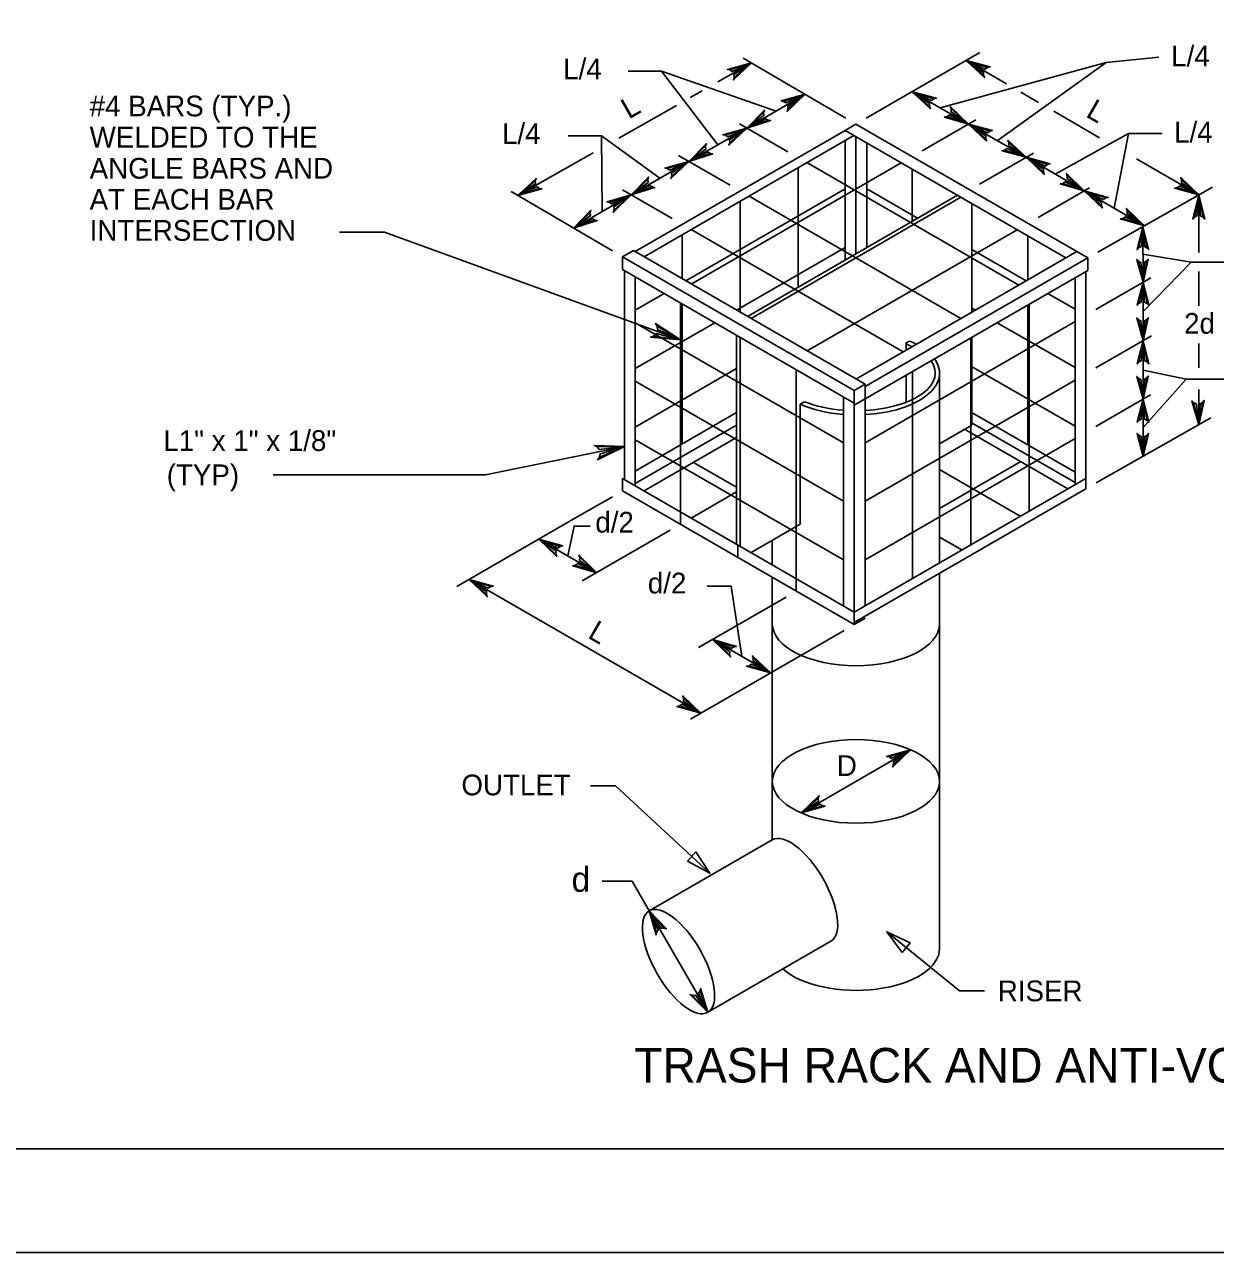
# Model space of a CAD drawing. Extents: x 636462 to 639890, y 299944 to 300538.
# Drawn here: x 637624.9 to 637797.1, y 299944.4 to 300122 of the extents above; entities that cross this region are included whole.
import ezdxf

# ---------------------------------------------------------------- set-up
doc = ezdxf.new("R2010")
doc.units = 0
for name, color, linetype in [('1', 7, 'Continuous'), ('Default', 7, 'Continuous'), ('PLT-BNDY', 7, 'Continuous')]:
    doc.layers.add(name, color=color, linetype=linetype)

msp = doc.modelspace()

# ---------------------------------------------------------------- linework, layer by layer
at = {"layer": '1'}
msp.add_lwpolyline([(638128.91, 299959.45), (638128.91, 300523.45), (637342.91, 300523.45), (637342.91, 299959.45), (638128.91, 299959.45), (638128.91, 299985.81), (637928.91, 299985.81), (637928.91, 300050.49), (638128.91, 300050.49), (638128.91, 300079.45), (637928.91, 300079.45), (637928.91, 299959.45), (638007.72, 299959.45), (638007.72, 299985.81), (638007.72, 299959.45), (638084.72, 299959.45), (638084.72, 299985.81), (638084.72, 299973.49), (638128.91, 299973.49)], dxfattribs=at)
at = {"layer": 'Default'}
for p, q in [((637746.61, 300108.45), (637763.05, 300117.94)), ((637743.68, 300108.46), (637728.84, 300117.16)), ((637765.56, 300105.2), (637781.31, 300116.52)), ((637733.58, 300109.48), (637717.03, 300115.25)), ((637729.36, 300107.04), (637737.79, 300111.91)), ((637720.99, 300102.21), (637729.36, 300107.04)), ((637735.3, 300103.61), (637728.3, 300107.66)), ((637743.57, 300106.69), (637745.14, 300107.6)), ((637745.14, 300107.6), (637778.64, 300088.26)), ((637754.72, 300103.76), (637762.45, 300108.22)), ((637761.39, 300107.61), (637769.73, 300102.8)), ((637708.46, 300094.97), (637708.33, 300105.89)), ((637713.22, 300089.17), (637743.57, 300106.69)), ((637714.5, 300088.43), (637744.85, 300105.95)), ((637743.57, 300106.69), (637775.5, 300088.26)), ((637743.57, 300105.22), (637743.57, 300087.96)), ((637745.14, 300105.79), (637745.14, 300088.87)), ((637782.49, 300095.43), (637784.55, 300106.23)), ((637746.71, 300104.88), (637746.71, 300089.77)), ((637763, 300098.91), (637770.79, 300103.41)), ((637712.62, 300097.37), (637720.99, 300102.21)), ((637726.93, 300098.78), (637719.49, 300103.07)), ((637721.33, 300084.48), (637751.69, 300102.01)), ((637768.7, 300084.33), (637738.05, 300102.03)), ((637769.72, 300102.8), (637778.13, 300097.94)), ((637736.77, 300101.29), (637736.77, 300084.03)), ((637753.26, 300101.1), (637753.26, 300093.55)), ((637718.56, 300093.94), (637711.36, 300098.1)), ((637720.55, 300084.94), (637743.57, 300098.23)), ((637754.04, 300094), (637746.71, 300098.23)), ((637771.47, 300094.09), (637778.89, 300098.38)), ((637780.11, 300089.1), (637796.7, 300098.5)), ((637709.93, 300089.27), (637695.28, 300097.85)), ((637704.3, 300092.57), (637712.62, 300097.37)), ((637728.4, 300096.45), (637728.4, 300080.4)), ((637729.44, 300079.8), (637759.8, 300097.33)), ((637760.32, 300079.5), (637729.68, 300097.19)), ((637729.97, 300079.5), (637760.32, 300097.02)), ((637778.13, 300097.94), (637786.85, 300092.91)), ((637761.89, 300096.12), (637761.89, 300080.4)), ((637786.63, 300092.79), (637786.64, 300084.73)), ((637720.02, 300091.62), (637720.02, 300085.24)), ((637751.95, 300074.66), (637721.3, 300092.36)), ((637738.08, 300074.81), (637768.43, 300092.34)), ((637770, 300091.43), (637770, 300085.09)), ((637711.39, 300088.41), (637712.96, 300089.32)), ((637712.96, 300089.32), (637746.45, 300069.98)), ((637713.22, 300089.17), (637713.22, 300089.17)), ((637727.87, 300080.71), (637743.57, 300089.77)), ((637752.39, 300074.92), (637777.07, 300089.17)), ((637769.74, 300084.94), (637761.89, 300089.47)), ((637711.39, 300086.6), (637711.39, 300088.41)), ((637744.88, 300069.07), (637711.39, 300088.41)), ((637714.5, 300088.43), (637714.5, 300088.43)), ((637746.45, 300069.68), (637778.64, 300088.26)), ((637778.64, 300086.45), (637778.64, 300088.26)), ((637786.64, 300080.51), (637793.6, 300087.62)), ((637744.88, 300067.26), (637711.39, 300086.6)), ((637711.65, 300086.45), (637711.65, 300056.23)), ((637711.65, 300086.45), (637711.65, 300086.45)), ((637744.88, 300066.96), (637778.64, 300086.45)), ((637778.38, 300086.3), (637778.38, 300056.38)), ((637713.22, 300085.54), (637713.22, 300055.32)), ((637776.81, 300085.39), (637776.81, 300055.48)), ((637779.84, 300080.8), (637787.76, 300085.38)), ((637786.64, 300084.73), (637786.64, 300076.27)), ((637713.22, 300080.71), (637717.41, 300083.12)), ((637776.81, 300080.86), (637772.88, 300083.12)), ((637719.76, 300081.76), (637719.76, 300051.55)), ((637720.02, 300081.61), (637720.02, 300061.37)), ((637761.89, 300081.01), (637762.41, 300080.71)), ((637770, 300081.46), (637770, 300061.22)), ((637770.2, 300081.58), (637770.2, 300051.66)), ((637713.22, 300072.25), (637724.73, 300078.89)), ((637743.31, 300061.52), (637713.22, 300078.89)), ((637746.45, 300061.52), (637776.81, 300079.05)), ((637776.81, 300072.4), (637765.56, 300078.89)), ((637727.87, 300077.08), (637727.87, 300046.86)), ((637728.4, 300076.78), (637728.4, 300046.56)), ((637761.76, 300076.7), (637761.76, 300046.79)), ((637761.89, 300076.83), (637761.89, 300064.09)), ((637779.84, 300072.34), (637787.86, 300076.98)), ((637745.14, 300070.74), (637752.39, 300074.92)), ((637752.39, 300075.96), (637752.88, 300076.24)), ((637752.39, 300074.92), (637752.39, 300075.96)), ((637752.5, 300075.78), (637752.39, 300075.96)), ((637753.28, 300075.44), (637753.28, 300075.44)), ((637753.88, 300075.78), (637753.88, 300075.78)), ((637786.64, 300076.27), (637786.65, 300067.81)), ((637755.99, 300073.37), (637755.99, 300073.37)), ((637756.49, 300073.66), (637756.49, 300073.66)), ((637713.22, 300063.79), (637727.87, 300072.25)), ((637736.51, 300072.1), (637736.51, 300041.88)), ((637753.32, 300071.83), (637753.32, 300041.92)), ((637757.22, 300044.16), (637757.22, 300071.61)), ((637776.81, 300063.93), (637761.76, 300072.62)), ((637743.31, 300053.06), (637713.22, 300070.43)), ((637746.45, 300069.98), (637744.88, 300069.07)), ((637746.45, 300053.06), (637776.81, 300070.58)), ((637746.45, 300069.98), (637746.45, 300037.95)), ((637746.45, 300069.68), (637746.45, 300069.68)), ((637752.39, 300067.39), (637752.39, 300071.29)), ((637786.65, 300063.71), (637792.89, 300070.72)), ((637743.31, 300068.17), (637743.31, 300044.6)), ((637744.88, 300069.07), (637744.88, 300067.26)), ((637779.84, 300063.87), (637787.74, 300068.45)), ((637786.65, 300067.81), (637786.66, 300059.56)), ((637737.06, 300067.11), (637737.68, 300067.46)), ((637737.06, 300049.75), (637737.06, 300067.11)), ((637737.68, 300067.46), (637737.68, 300067.46)), ((637743.31, 300066.24), (637743.31, 300066.24)), ((637744.88, 300067.26), (637744.88, 300037.04)), ((637746.45, 300066.2), (637746.45, 300066.2)), ((637713.22, 300057.44), (637727.87, 300065.9)), ((637743.31, 300065.63), (637743.31, 300065.63)), ((637746.45, 300065.6), (637746.45, 300065.6)), ((637776.81, 300057.29), (637762.02, 300065.82)), ((637776.81, 300055.78), (637762.02, 300064.31)), ((637779.85, 300055.71), (637796.43, 300065.11)), ((637713.22, 300055.63), (637727.87, 300064.09)), ((637757.22, 300061.39), (637761.89, 300064.09)), ((637775.76, 300054.87), (637760.85, 300063.48)), ((637778.38, 300063.03), (637778.37, 300063.03)), ((637743.31, 300044.6), (637713.22, 300061.97)), ((637714.53, 300054.57), (637727.87, 300062.27)), ((637746.45, 300044.6), (637776.81, 300062.12)), ((637727.87, 300055.1), (637721.66, 300058.69)), ((637757.22, 300052.02), (637768.96, 300058.8)), ((637768.89, 300050.9), (637757.22, 300057.65)), ((637711.39, 300056.38), (637711.39, 300054.57)), ((637744.88, 300037.04), (637711.39, 300056.38)), ((637744.88, 300037.04), (637778.38, 300056.38)), ((637778.38, 300056.38), (637778.38, 300054.87)), ((637709.92, 300053.72), (637704.6, 300050.65)), ((637711.39, 300054.57), (637744.88, 300035.23)), ((637721.33, 300050.64), (637727.87, 300054.42)), ((637778.38, 300054.87), (637744.88, 300035.53)), ((637704.6, 300050.65), (637687.43, 300040.74)), ((637719.76, 300051.55), (637719.76, 300049.73)), ((637718.29, 300048.89), (637705.57, 300041.54)), ((637729.97, 300045.65), (637737.06, 300049.75)), ((637737.06, 300049.75), (637737.06, 300049.75)), ((637707.65, 300042.74), (637699.28, 300047.58)), ((637728.04, 300046.76), (637728.04, 300044.95)), ((637733.04, 300047.43), (637733.04, 300043.88)), ((637760.45, 300046.03), (637757.22, 300047.9)), ((637743.31, 300044.76), (637743.31, 300037.95)), ((637733.04, 300042.07), (637733.04, 300035.34)), ((637736.51, 300041.88), (637736.51, 300040.06)), ((637757.22, 300035.34), (637757.22, 300042.65)), ((637735.04, 300039.22), (637722.39, 300031.92)), ((637744.88, 300035.23), (637744.88, 300037.04)), ((637744.88, 300035.23), (637746.45, 300036.14)), ((637733.04, 300035.34), (637733.04, 300013)), ((637743.42, 300034.38), (637738.1, 300031.31)), ((637757.22, 300035.34), (637757.22, 300012.56)), ((637724.4, 300033.07), (637732.77, 300028.24)), ((637738.09, 300031.31), (637721.19, 300021.55)), ((637706.76, 300011.93), (637710.36, 300011.93)), ((637724.03, 299999.27), (637710.36, 300011.93)), ((637733.04, 300012.56), (637733.04, 300004.1)), ((637757.22, 300012.56), (637757.22, 299988.39)), ((637733.04, 300004.1), (637715.25, 299993.83)), ((637733.04, 300004.1), (637733.04, 300004.1)), ((637708.46, 299998.14), (637712.76, 299998.14)), ((637749.59, 299990.81), (637760.1, 299982.27)), ((637741.5, 299989.45), (637723.71, 299979.17)), ((637734.57, 299985.45), (637734.57, 299985.45)), ((637763.7, 299982.27), (637760.1, 299982.27))]:
    msp.add_line(p, q, dxfattribs=at)
for points in [[(637730.02, 300116.47), (637725.16, 300113.71)], [(637726.89, 300115.45), (637726.55, 300115.51), (637730.02, 300116.47), (637726.89, 300115.45), (637727.24, 300115.22), (637730.02, 300116.47), (637727.5, 300114.76), (637727.53, 300114.35), (637730.02, 300116.47), (637727.41, 300113.99), (637727.53, 300114.35)], [(637788.91, 300117.26), (637781.31, 300116.52), (637757.33, 300109.95)], [(637763.57, 300114.66), (637763.7, 300114.34), (637761.05, 300116.79), (637763.57, 300114.66), (637763.58, 300115.08), (637761.05, 300116.79), (637763.83, 300115.54), (637764.17, 300115.78), (637761.05, 300116.79), (637764.54, 300115.87), (637764.17, 300115.78)], [(637766.89, 300113.41), (637761.05, 300116.79)], [(637712.2, 300115.25), (637717.03, 300115.25), (637725.18, 300104.62)], [(637722.9, 300112.42), (637721.18, 300111.44)], [(637755.78, 300110.15), (637755.9, 300109.83), (637753.27, 300112.29), (637755.78, 300110.15), (637755.79, 300110.57), (637753.27, 300112.29), (637756.04, 300111.03), (637756.38, 300111.27), (637753.27, 300112.29), (637756.76, 300111.35), (637756.38, 300111.27)], [(637761.39, 300107.61), (637753.27, 300112.29)], [(637771.54, 300110.73), (637768.99, 300112.2)], [(637734.66, 300110.89), (637734.32, 300110.95), (637737.79, 300111.91), (637734.66, 300110.89), (637735.02, 300110.66), (637737.79, 300111.91), (637735.28, 300110.2), (637735.3, 300109.79), (637737.79, 300111.91), (637735.18, 300109.43), (637735.3, 300109.79)], [(637719.19, 300110.31), (637710.87, 300105.58)], [(637732.46, 300108.18), (637732.8, 300108.13), (637729.36, 300107.04), (637732.46, 300108.18), (637732.09, 300108.39), (637729.36, 300107.04), (637731.82, 300108.84), (637731.78, 300109.25), (637729.36, 300107.04), (637731.89, 300109.62), (637731.78, 300109.25)], [(637758.92, 300109.79), (637758.8, 300110.12), (637761.39, 300107.61), (637758.92, 300109.79), (637758.9, 300109.37), (637761.39, 300107.61), (637758.64, 300108.92), (637758.29, 300108.68), (637761.39, 300107.61), (637757.92, 300108.61), (637758.29, 300108.68)], [(637780.37, 300105.63), (637773.73, 300109.47)], [(637726.24, 300106.01), (637725.89, 300106.07), (637729.36, 300107.04), (637726.24, 300106.01), (637726.59, 300105.78), (637729.36, 300107.04), (637726.85, 300105.33), (637726.88, 300104.91), (637729.36, 300107.04), (637726.76, 300104.55), (637726.88, 300104.91)], [(637763.89, 300105.47), (637764.02, 300105.14), (637761.39, 300107.61), (637763.89, 300105.47), (637763.9, 300105.89), (637761.39, 300107.61), (637764.15, 300106.35), (637764.5, 300106.59), (637761.39, 300107.61), (637764.87, 300106.67), (637764.5, 300106.59)], [(637703.5, 300105.89), (637708.33, 300105.89), (637716.8, 300099.79)], [(637767.23, 300104.95), (637767.11, 300105.28), (637769.73, 300102.8), (637767.23, 300104.95), (637767.22, 300104.53), (637769.73, 300102.8), (637766.96, 300104.07), (637766.62, 300103.83), (637769.73, 300102.8), (637766.25, 300103.75), (637766.62, 300103.83)], [(637789.39, 300106.23), (637784.55, 300106.23), (637773.93, 300100.37)], [(637696.26, 300097.28), (637707.14, 300103.46)], [(637724.08, 300103.34), (637724.43, 300103.29), (637720.99, 300102.21), (637724.08, 300103.34), (637723.72, 300103.56), (637720.99, 300102.21), (637723.44, 300104), (637723.4, 300104.42), (637720.99, 300102.21), (637723.51, 300104.78), (637723.4, 300104.42)], [(637717.86, 300101.19), (637717.51, 300101.25), (637720.99, 300102.21), (637717.86, 300101.19), (637718.21, 300100.96), (637720.99, 300102.21), (637718.47, 300100.51), (637718.49, 300100.09), (637720.99, 300102.21), (637718.37, 300099.73), (637718.49, 300100.09)], [(637772.23, 300100.66), (637772.35, 300100.33), (637769.73, 300102.8), (637772.23, 300100.66), (637772.24, 300101.08), (637769.73, 300102.8), (637772.49, 300101.54), (637772.83, 300101.77), (637769.73, 300102.8), (637773.21, 300101.86), (637772.83, 300101.77)], [(637794.69, 300097.36), (637785.7, 300102.56)], [(637715.71, 300098.51), (637716.05, 300098.46), (637712.62, 300097.37), (637715.71, 300098.51), (637715.35, 300098.72), (637712.62, 300097.37), (637715.07, 300099.17), (637715.03, 300099.58), (637712.62, 300097.37), (637715.14, 300099.95), (637715.03, 300099.58)], [(637712.62, 300097.37), (637716.82, 300099.79)], [(637775.68, 300100.14), (637775.56, 300100.47), (637778.13, 300097.94), (637775.68, 300100.14), (637775.66, 300099.72), (637778.13, 300097.94), (637775.4, 300099.26), (637775.05, 300099.03), (637778.13, 300097.94), (637774.68, 300098.96), (637775.05, 300099.03)], [(637792.22, 300099.54), (637792.1, 300099.87), (637794.69, 300097.36), (637792.22, 300099.54), (637792.21, 300099.12), (637794.69, 300097.36), (637791.95, 300098.66), (637791.6, 300098.43), (637794.69, 300097.36), (637791.23, 300098.36), (637791.6, 300098.43)], [(637699.39, 300098.3), (637699.74, 300098.24), (637696.26, 300097.28), (637699.39, 300098.3), (637699.04, 300098.53), (637696.26, 300097.28), (637698.78, 300098.98), (637698.76, 300099.4), (637696.26, 300097.28), (637698.88, 300099.76), (637698.76, 300099.4)], [(637709.5, 300096.29), (637709.16, 300096.35), (637712.62, 300097.37), (637709.5, 300096.29), (637709.86, 300096.07), (637712.62, 300097.37), (637710.13, 300095.62), (637710.16, 300095.21), (637712.62, 300097.37), (637710.05, 300094.84), (637710.16, 300095.21)], [(637780.64, 300095.8), (637780.76, 300095.47), (637778.13, 300097.94), (637780.64, 300095.8), (637780.65, 300096.22), (637778.13, 300097.94), (637780.9, 300096.68), (637781.24, 300096.92), (637778.13, 300097.94), (637781.62, 300097), (637781.24, 300096.92)], [(637794.06, 300094.13), (637793.83, 300093.86), (637794.7, 300097.36), (637794.06, 300094.13), (637794.43, 300094.33), (637794.7, 300097.36), (637794.95, 300094.33), (637795.33, 300094.15), (637794.7, 300097.36), (637795.58, 300093.87), (637795.33, 300094.15)], [(637794.7, 300097.36), (637794.7, 300089.04)], [(637707.39, 300093.7), (637707.74, 300093.65), (637704.3, 300092.57), (637707.39, 300093.7), (637707.03, 300093.92), (637704.3, 300092.57), (637706.75, 300094.37), (637706.71, 300094.78), (637704.3, 300092.57), (637706.82, 300095.14), (637706.71, 300094.78)], [(637784.37, 300095.08), (637784.25, 300095.41), (637786.85, 300092.91), (637784.37, 300095.08), (637784.35, 300094.66), (637786.85, 300092.91), (637784.09, 300094.21), (637783.75, 300093.97), (637786.85, 300092.91), (637783.38, 300093.9), (637783.75, 300093.97)], [(637786, 300089.72), (637785.79, 300089.47), (637786.63, 300092.79), (637786, 300089.72), (637786.36, 300089.91), (637786.63, 300092.79), (637786.86, 300089.91), (637787.21, 300089.73), (637786.63, 300092.79), (637787.45, 300089.46), (637787.21, 300089.73)], [(637719.76, 300076.39), (637676.96, 300091.99), (637670.45, 300091.99)], [(637787.18, 300087.81), (637787.39, 300088.07), (637786.64, 300084.73), (637787.18, 300087.81), (637786.83, 300087.62), (637786.64, 300084.73), (637786.34, 300087.6), (637785.98, 300087.77), (637786.64, 300084.73), (637785.73, 300088.03), (637785.98, 300087.77)], [(637798.44, 300087.62), (637793.6, 300087.62), (637786.63, 300088.82)], [(637794.7, 300086.31), (637794.7, 300081.31)], [(637786.01, 300081.66), (637785.79, 300081.41), (637786.64, 300084.73), (637786.01, 300081.66), (637786.36, 300081.85), (637786.64, 300084.73), (637786.86, 300081.85), (637787.22, 300081.67), (637786.64, 300084.73), (637787.46, 300081.4), (637787.22, 300081.67)], [(637716.37, 300078.41), (637716.15, 300078.77), (637719.76, 300076.39), (637716.37, 300078.41), (637716.44, 300077.91), (637719.76, 300076.39), (637716.23, 300077.32), (637715.87, 300076.96), (637719.76, 300076.39), (637715.45, 300076.79), (637715.87, 300076.96)], [(637787.18, 300079.35), (637787.39, 300079.61), (637786.64, 300076.27), (637787.18, 300079.35), (637786.83, 300079.16), (637786.64, 300076.27), (637786.34, 300079.14), (637785.97, 300079.31), (637786.64, 300076.27), (637785.73, 300079.57), (637785.97, 300079.31)], [(637786.02, 300073.21), (637785.8, 300072.95), (637786.64, 300076.27), (637786.02, 300073.21), (637786.37, 300073.39), (637786.64, 300076.27), (637786.87, 300073.39), (637787.22, 300073.22), (637786.64, 300076.27), (637787.46, 300072.95), (637787.22, 300073.22)], [(637794.7, 300072.38), (637794.7, 300075.89)], [(637800.14, 300070.72), (637795.31, 300070.72), (637792.89, 300070.72), (637786.65, 300072.04)], [(637787.19, 300070.9), (637787.4, 300071.16), (637786.65, 300067.81), (637787.19, 300070.9), (637786.84, 300070.7), (637786.65, 300067.81), (637786.34, 300070.69), (637785.98, 300070.85), (637786.65, 300067.81), (637785.74, 300071.11), (637785.98, 300070.85)], [(637786.02, 300064.75), (637785.8, 300064.5), (637786.65, 300067.81), (637786.02, 300064.75), (637786.37, 300064.93), (637786.65, 300067.81), (637786.87, 300064.93), (637787.22, 300064.76), (637786.65, 300067.81), (637787.46, 300064.49), (637787.22, 300064.76)], [(637794.7, 300064.12), (637794.7, 300069.24)], [(637795.25, 300067.37), (637795.47, 300067.64), (637794.7, 300064.12), (637795.25, 300067.37), (637794.89, 300067.16), (637794.7, 300064.12), (637794.36, 300067.14), (637793.98, 300067.32), (637794.7, 300064.12), (637793.72, 300067.59), (637793.98, 300067.32)], [(637787.24, 300062.64), (637787.45, 300062.89), (637786.66, 300059.56), (637787.24, 300062.64), (637786.89, 300062.45), (637786.66, 300059.56), (637786.39, 300062.44), (637786.03, 300062.61), (637786.66, 300059.56), (637785.79, 300062.88), (637786.03, 300062.61)], [(637711.65, 300061.01), (637691.58, 300056.89), (637660.88, 300056.89)], [(637707.7, 300060.93), (637707.32, 300061.12), (637711.65, 300061.01), (637707.7, 300060.93), (637708.02, 300060.54), (637711.65, 300061.01), (637708.16, 300059.93), (637708.05, 300059.44), (637711.65, 300061.01), (637707.78, 300059.07), (637708.05, 300059.44)], [(637706.71, 300049.48), (637704.37, 300049.48), (637703.47, 300045.16)], [(637701.76, 300045.41), (637701.88, 300045.09), (637699.28, 300047.58), (637701.76, 300045.41), (637701.78, 300045.84), (637699.28, 300047.58), (637702.03, 300046.29), (637702.38, 300046.53), (637699.28, 300047.58), (637702.75, 300046.61), (637702.38, 300046.53)], [(637705.19, 300044.93), (637705.07, 300045.26), (637707.65, 300042.74), (637705.19, 300044.93), (637705.17, 300044.51), (637707.65, 300042.74), (637704.91, 300044.05), (637704.56, 300043.82), (637707.65, 300042.74), (637704.19, 300043.75), (637704.56, 300043.82)], [(637691.7, 300039.61), (637691.82, 300039.28), (637689.21, 300041.77), (637691.7, 300039.61), (637691.72, 300040.03), (637689.21, 300041.77), (637691.97, 300040.49), (637692.32, 300040.72), (637689.21, 300041.77), (637692.69, 300040.8), (637692.32, 300040.72)], [(637689.21, 300041.77), (637722.71, 300022.43)], [(637723.61, 300040.77), (637727.09, 300040.77), (637728.62, 300030.64)], [(637726.87, 300030.89), (637726.99, 300030.56), (637724.4, 300033.07), (637726.87, 300030.89), (637726.89, 300031.31), (637724.4, 300033.07), (637727.15, 300031.77), (637727.49, 300032), (637724.4, 300033.07), (637727.86, 300032.07), (637727.49, 300032)], [(637730.29, 300030.41), (637730.17, 300030.73), (637732.77, 300028.24), (637730.29, 300030.41), (637730.27, 300029.98), (637732.77, 300028.24), (637730.02, 300029.53), (637729.67, 300029.29), (637732.77, 300028.24), (637729.3, 300029.21), (637729.67, 300029.29)], [(637720.22, 300024.59), (637720.1, 300024.92), (637722.71, 300022.43), (637720.22, 300024.59), (637720.21, 300024.17), (637722.71, 300022.43), (637719.95, 300023.72), (637719.61, 300023.48), (637722.71, 300022.43), (637719.24, 300023.4), (637719.61, 300023.48)], [(637753.04, 300017.13), (637737.22, 300007.99)], [(637749.92, 300016.09), (637749.57, 300016.15), (637753.04, 300017.13), (637749.92, 300016.09), (637750.27, 300015.86), (637753.04, 300017.13), (637750.54, 300015.41), (637750.56, 300014.99), (637753.04, 300017.13), (637750.44, 300014.63), (637750.56, 300014.99)], [(637740.34, 300009.05), (637740.68, 300008.99), (637737.22, 300008), (637740.34, 300009.05), (637739.98, 300009.27), (637737.22, 300008), (637739.72, 300009.72), (637739.69, 300010.14), (637737.22, 300008), (637739.81, 300010.5), (637739.69, 300010.14)], [(637715.25, 299993.83), (637712.76, 299998.14)], [(637716.29, 299990.7), (637716.23, 299990.36), (637715.25, 299993.83), (637716.29, 299990.7), (637716.52, 299991.06), (637715.25, 299993.83), (637716.97, 299991.32), (637717.38, 299991.35), (637715.25, 299993.83), (637717.74, 299991.23), (637717.38, 299991.35)], [(637715.25, 299993.83), (637723.71, 299979.17)], [(637722.61, 299982.28), (637722.66, 299982.62), (637723.71, 299979.17), (637722.61, 299982.28), (637722.39, 299981.92), (637723.71, 299979.17), (637721.94, 299981.65), (637721.52, 299981.61), (637723.71, 299979.17), (637721.16, 299981.73), (637721.52, 299981.61)]]:
    msp.add_lwpolyline(points, dxfattribs=at)
for points in [[(637722, 300002.37), (637724.03, 299999.27), (637720.78, 300001.05)], [(637751.81, 299987.84), (637749.59, 299990.81), (637752.95, 299989.24)]]:
    msp.add_lwpolyline(points, close=True, dxfattribs=at)
for centre, major_axis, ratio, start_param, end_param in [((637745.13, 300071.6), (11.48, 0), 0.473684, 0.781137, 0.874306), ((637745.13, 300071.6), (12.09, 0), 0.5, 0.7618, 0.874306), ((637745.13, 300071.6), (12.09, 0), 0.5, 4.82209, 6.630569), ((637745.13, 300071.6), (11.48, 0), 0.473684, 4.827888, 6.613889), ((637745.13, 300071.6), (12.09, 0), 0.5, 3.981444, 4.561497), ((637745.13, 300071.6), (11.48, 0), 0.473684, 4.006763, 4.553489), ((637745.13, 300035.34), (12.09, 0), 0.5, 3.141593, 6.283185), ((637745.13, 300012.56), (12.09, 0), 0.5, 0, 6.283175), ((637737.27, 299996.78), (-4.23, 7.33), 0.41917, 3.141593, 6.283185), ((637719.48, 299986.5), (-4.23, 7.33), 0.41917, 0, 6.283175), ((637745.13, 299988.39), (12.09, 0), 0.5, 3.650223, 6.283185)]:
    msp.add_ellipse(centre, major_axis=major_axis, ratio=ratio, start_param=start_param, end_param=end_param, dxfattribs=at)
at = {"layer": 'PLT-BNDY'}
msp.add_lwpolyline([(637302.91, 300538.45), (638143.91, 300538.45), (638143.91, 299944.45), (637302.91, 299944.45)], close=True, dxfattribs=at)

# ---------------------------------------------------------------- texts
at = {"layer": 'Default'}
for s, height, p in [('L/4', 2.998, (637790.71, 300115.94)), ('L/4', 2.998, (637702.8, 300114.08)), ('#4 BARS (TYP.) ', 2.9979, (637634.34, 300108.72)), ('WELDED TO THE', 2.9979, (637634.34, 300104.22)), ('L/4', 2.998, (637693.96, 300104.74)), ('L/4', 2.998, (637791.13, 300104.94)), ('ANGLE BARS AND', 2.9979, (637634.34, 300099.72)), ('AT EACH BAR', 2.9979, (637634.34, 300095.23)), ('INTERSECTION ', 2.9979, (637634.34, 300090.73)), ('2d', 2.998, (637792.58, 300077.3)), ('L1" x 1" x 1/8"', 2.9979, (637644.99, 300060.34)), ('(TYP)', 2.998, (637645.48, 300055.39)), ('d/2', 2.998, (637707.45, 300048.54)), ('d/2', 2.998, (637715.04, 300039.74)), ('D', 3, (637742.37, 300013.35)), ('OUTLET', 2.998, (637688.09, 300010.55)), ('d', 3.6, (637704.02, 299996.6)), ('RISER', 2.998, (637765.64, 299980.77)), ('TRASH RACK AND ANTI-VORTEX DEVICE', 4.9967, (637713.07, 299969.02))]:
    msp.add_text(s, height=height, dxfattribs=at).set_placement(p)
for rotation, p in [(29.6143, (637712.29, 300108.26)), (330.0001, (637778.22, 300108.76)), (330.0001, (637706.21, 300033.4))]:
    msp.add_text('L', height=3, rotation=rotation, dxfattribs=at).set_placement(p)

doc.saveas('drawing.dxf')
